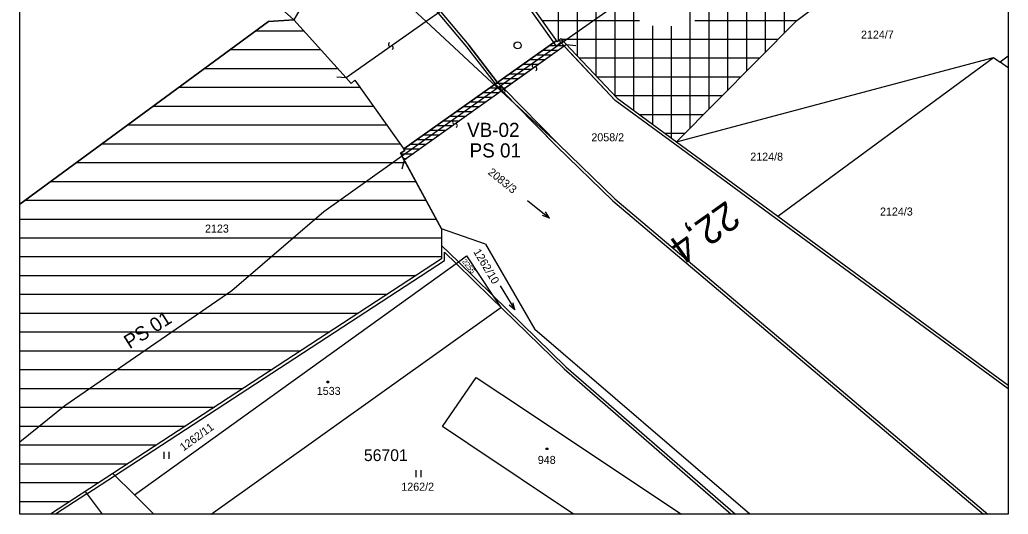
# Model space of a CAD drawing. Extents: x -792659 to -786947, y -1118170 to -1109641.
# Drawn here: x -792453.4 to -792348.4, y -1109997.6 to -1109945.1 of the extents above; entities that cross this region are included whole.
import ezdxf

# ---------------------------------------------------------------- set-up
doc = ezdxf.new("R2010")
doc.units = 0
doc.layers.add('1', color=7, linetype='Continuous')

# ---------------------------------------------------------------- blocks, each defined once
blk = doc.blocks.new('Z4022')
at = {"layer": '1'}
for p, q in [((-0.1, 0.1), (0.2, 0.1)), ((-0.1, -0.2), (-0.1, 0.1)), ((0.2, 0.1), (0.2, -0.2)), ((0.2, -0.2), (-0.1, -0.2))]:
    blk.add_line(p, q, dxfattribs=at)
blk = doc.blocks.new('Z42000')
at = {"layer": '1'}
blk.add_line((0, 0), (-0.7, -0.7), dxfattribs=at)
blk = doc.blocks.new('Z30602')
at = {"layer": '1'}
for p, q in [((-0.5, 0), (-0.5, 1.5)), ((0.5, 1.5), (0.5, 0))]:
    blk.add_line(p, q, dxfattribs=at)
blk = doc.blocks.new('Z8021')
at = {"layer": '1'}
for p, q in [((-3, 0), (3, 0)), ((3, 0), (1.5, 0.5)), ((3, 0), (1.5, -0.5))]:
    blk.add_line(p, q, dxfattribs=at)

msp = doc.modelspace()

# ---------------------------------------------------------------- linework, layer by layer
at = {"layer": '1'}
for p, q in [((-792372.2, -1109946.49), (-792372.2, -1109865.86)), ((-792376.2, -1109950.53), (-792376.2, -1109867.84)), ((-792374.2, -1109948.51), (-792374.2, -1109866.85)), ((-792378.2, -1109952.54), (-792378.2, -1109868.83)), ((-792380.2, -1109954.56), (-792380.2, -1109869.82)), ((-792382.2, -1109956.58), (-792382.2, -1109870.81)), ((-792392.2, -1109951.08), (-792392.2, -1109882.8)), ((-792394.2, -1109948.95), (-792394.2, -1109884.32)), ((-792396.2, -1109947.31), (-792396.2, -1109885.85)), ((-792390.2, -1109953.09), (-792390.2, -1109918.38)), ((-792388.2, -1109954.75), (-792388.2, -1109918.33)), ((-792410.26, -1109945.28), (-792419.34, -1109936.86)), ((-792420.84, -1109939.05), (-792424.33, -1109945.11)), ((-792396.41, -1109947.92), (-792402.08, -1109939.9)), ((-792401.63, -1109940.01), (-792396.36, -1109947.46)), ((-792389.4, -1109943.05), (-792401.43, -1109951.47)), ((-792424.33, -1109945.11), (-792425.94, -1109943.64)), ((-792408.74, -1109944.21), (-792410.26, -1109945.28)), ((-792408.74, -1109944.21), (-792405.73, -1109947.8)), ((-792427.01, -1109945.27), (-792453.43, -1109964.69)), ((-792427.01, -1109945.27), (-792453.43, -1109964.69)), ((-792424.33, -1109945.11), (-792427.01, -1109945.27)), ((-792424.33, -1109945.11), (-792427.01, -1109945.27)), ((-792424.33, -1109945.11), (-792418.77, -1109951.27)), ((-792424.33, -1109945.11), (-792418.77, -1109951.27)), ((-792410.26, -1109945.28), (-792418.77, -1109951.27)), ((-792402.3, -1109952.67), (-792410.26, -1109945.28)), ((-792402.3, -1109952.67), (-792410.26, -1109945.28)), ((-792397.99, -1109945.16), (-792387.61, -1109945.16)), ((-792381.73, -1109945.16), (-792370.88, -1109945.16)), ((-792428.37, -1109946.27), (-792423.28, -1109946.27)), ((-792386.2, -1109956.22), (-792386.2, -1109945.76)), ((-792384.2, -1109957.69), (-792384.2, -1109945.79)), ((-792396.44, -1109947.34), (-792412.63, -1109958.83)), ((-792396.36, -1109947.46), (-792396.44, -1109947.34)), ((-792396.41, -1109947.92), (-792395.97, -1109947.51)), ((-792396.36, -1109947.46), (-792395.96, -1109947.08)), ((-792395.96, -1109947.08), (-792396.36, -1109947.46)), ((-792396.22, -1109947.33), (-792395.73, -1109947.33)), ((-792395.97, -1109947.51), (-792390.18, -1109953.67)), ((-792395.96, -1109947.08), (-792395.36, -1109947.72)), ((-792395.36, -1109947.72), (-792395.96, -1109947.08)), ((-792395.89, -1109947.16), (-792372.86, -1109947.16)), ((-792431.09, -1109948.27), (-792421.48, -1109948.27)), ((-792402.71, -1109951.72), (-792405.73, -1109947.8)), ((-792405.73, -1109947.8), (-792402.71, -1109951.72)), ((-792395.36, -1109947.72), (-792401.99, -1109952.45)), ((-792397.83, -1109948.33), (-792396.21, -1109948.33)), ((-792397.13, -1109947.83), (-792395.51, -1109947.83)), ((-792394.9, -1109948.21), (-792395.36, -1109947.72)), ((-792389.98, -1109953.44), (-792394.9, -1109948.21)), ((-792399.24, -1109949.33), (-792397.61, -1109949.33)), ((-792398.54, -1109948.83), (-792396.92, -1109948.83)), ((-792394.01, -1109949.16), (-792374.85, -1109949.16)), ((-792383.68, -1109958.07), (-792350, -1109949.1)), ((-792372.92, -1109965.97), (-792350, -1109949.1)), ((-792350, -1109949.1), (-792349.29, -1109949.6)), ((-792348.43, -1109948.95), (-792349.29, -1109949.6)), ((-792348.43, -1109950.2), (-792349.29, -1109949.6)), ((-792433.81, -1109950.27), (-792419.67, -1109950.27)), ((-792400.65, -1109950.33), (-792399.02, -1109950.33)), ((-792399.95, -1109949.83), (-792398.32, -1109949.83)), ((-792401.43, -1109951.47), (-792421.14, -1109965.5)), ((-792418.77, -1109951.27), (-792419.76, -1109951.21)), ((-792418.22, -1109951.87), (-792418.77, -1109951.27)), ((-792418.77, -1109951.27), (-792418.22, -1109951.87)), ((-792418.22, -1109951.87), (-792417.83, -1109951.51)), ((-792418.22, -1109951.87), (-792417.83, -1109951.51)), ((-792417.83, -1109951.51), (-792412.51, -1109959)), ((-792417.83, -1109951.51), (-792412.51, -1109959)), ((-792402.77, -1109951.83), (-792401.12, -1109951.83)), ((-792402.71, -1109951.72), (-792401.99, -1109952.45)), ((-792402.71, -1109951.72), (-792401.99, -1109952.45)), ((-792402.06, -1109951.33), (-792400.42, -1109951.33)), ((-792401.36, -1109950.83), (-792399.72, -1109950.83)), ((-792392.12, -1109951.16), (-792376.83, -1109951.16)), ((-792436.53, -1109952.27), (-792417.29, -1109952.27)), ((-792402.3, -1109952.67), (-792412.59, -1109960.02)), ((-792404.18, -1109952.83), (-792402.52, -1109952.83)), ((-792403.47, -1109952.33), (-792401.82, -1109952.33)), ((-792402.94, -1109951.92), (-792396.42, -1109958.53)), ((-792401.99, -1109952.45), (-792402.3, -1109952.67)), ((-792396.21, -1109958.32), (-792402.3, -1109952.67)), ((-792401.99, -1109952.45), (-792396.21, -1109958.32)), ((-792405.58, -1109953.83), (-792403.92, -1109953.83)), ((-792404.88, -1109953.33), (-792403.22, -1109953.33)), ((-792390.24, -1109953.16), (-792378.81, -1109953.16)), ((-792389.98, -1109953.44), (-792383.68, -1109958.07)), ((-792439.26, -1109954.27), (-792415.87, -1109954.27)), ((-792406.99, -1109954.83), (-792405.32, -1109954.83)), ((-792406.29, -1109954.33), (-792404.62, -1109954.33)), ((-792408.4, -1109955.83), (-792406.72, -1109955.83)), ((-792407.7, -1109955.33), (-792406.02, -1109955.33)), ((-792387.64, -1109955.16), (-792380.8, -1109955.16)), ((-792441.98, -1109956.27), (-792414.45, -1109956.27)), ((-792409.81, -1109956.83), (-792408.12, -1109956.83)), ((-792409.11, -1109956.33), (-792407.42, -1109956.33)), ((-792411.22, -1109957.83), (-792409.52, -1109957.83)), ((-792410.52, -1109957.33), (-792408.82, -1109957.33)), ((-792384.92, -1109957.16), (-792382.78, -1109957.16)), ((-792383.68, -1109958.07), (-792372.92, -1109965.97)), ((-792444.7, -1109958.27), (-792413.03, -1109958.27)), ((-792412.51, -1109959), (-792413, -1109959.27)), ((-792412.51, -1109959), (-792413, -1109959.27)), ((-792412.63, -1109958.83), (-792410.92, -1109958.83)), ((-792411.93, -1109958.33), (-792410.22, -1109958.33)), ((-792396.21, -1109958.32), (-792390.22, -1109964.13)), ((-792413, -1109959.27), (-792412.59, -1109960.02)), ((-792413, -1109959.27), (-792408.62, -1109967.32)), ((-792412.97, -1109959.33), (-792411.62, -1109959.33)), ((-792412.59, -1109960.02), (-792412.84, -1109960.98)), ((-792412.69, -1109959.83), (-792412.32, -1109959.83)), ((-792408.62, -1109967.32), (-792412.59, -1109960.02)), ((-792447.42, -1109960.27), (-792412.46, -1109960.27)), ((-792450.14, -1109962.27), (-792411.37, -1109962.27)), ((-792452.86, -1109964.27), (-792410.28, -1109964.27)), ((-792390.22, -1109964.13), (-792350.58, -1109997.64)), ((-792453.43, -1109966.27), (-792409.19, -1109966.27)), ((-792421.14, -1109965.5), (-792430.91, -1109973.9)), ((-792372.92, -1109965.97), (-792348.43, -1109983.94)), ((-792408.62, -1109967.32), (-792408.62, -1109969.07)), ((-792403.95, -1109968.95), (-792408.62, -1109967.32)), ((-792408.62, -1109967.32), (-792408.62, -1109969.07)), ((-792453.43, -1109968.27), (-792408.62, -1109968.27)), ((-792408.62, -1109969.07), (-792406.84, -1109970.81)), ((-792408.62, -1109969.07), (-792408.62, -1109970.51)), ((-792408.62, -1109969.07), (-792408.62, -1109970.51)), ((-792403.95, -1109968.95), (-792398.71, -1109978)), ((-792453.43, -1109970.27), (-792408.62, -1109970.27)), ((-792408.62, -1109970.51), (-792443.53, -1109993.3)), ((-792408.62, -1109970.51), (-792443.53, -1109993.3)), ((-792406.84, -1109970.81), (-792405.98, -1109970.19)), ((-792405.98, -1109970.19), (-792403.21, -1109974.35)), ((-792441.26, -1109995.57), (-792406.84, -1109970.81)), ((-792406.84, -1109970.81), (-792403.21, -1109974.35)), ((-792453.43, -1109972.27), (-792411.32, -1109972.27)), ((-792430.91, -1109973.9), (-792448.63, -1109986.11)), ((-792453.43, -1109974.27), (-792414.38, -1109974.27)), ((-792403.21, -1109974.35), (-792402.34, -1109975.66)), ((-792403.21, -1109974.35), (-792395.41, -1109981.97)), ((-792433.1, -1109997.64), (-792402.34, -1109975.66)), ((-792453.43, -1109976.27), (-792417.44, -1109976.27)), ((-792375.89, -1109997.64), (-792398.71, -1109978)), ((-792453.43, -1109978.27), (-792420.51, -1109978.27)), ((-792453.43, -1109980.27), (-792423.57, -1109980.27)), ((-792453.43, -1109982.27), (-792426.63, -1109982.27)), ((-792395.41, -1109981.97), (-792377.41, -1109997.64)), ((-792408.53, -1109988.32), (-792404.94, -1109983.1)), ((-792404.94, -1109983.1), (-792402.24, -1109984.9)), ((-792453.43, -1109984.27), (-792429.7, -1109984.27)), ((-792402.24, -1109984.9), (-792383.15, -1109997.64)), ((-792448.63, -1109986.11), (-792453.43, -1109989.98)), ((-792453.43, -1109986.27), (-792432.76, -1109986.27)), ((-792453.43, -1109988.27), (-792435.83, -1109988.27)), ((-792405.83, -1109990.13), (-792408.53, -1109988.32)), ((-792453.43, -1109990.27), (-792438.89, -1109990.27)), ((-792394.62, -1109997.64), (-792405.83, -1109990.13)), ((-792453.43, -1109992.27), (-792441.95, -1109992.27)), ((-792443.53, -1109993.3), (-792450.18, -1109997.64)), ((-792443.53, -1109993.3), (-792450.18, -1109997.64)), ((-792443.53, -1109993.3), (-792441.26, -1109995.57)), ((-792443.52, -1109993.27), (-792443.48, -1109993.27)), ((-792453.43, -1109994.27), (-792445.02, -1109994.27)), ((-792441.26, -1109995.57), (-792439.18, -1109997.64)), ((-792453.43, -1109996.27), (-792448.08, -1109996.27))]:
    msp.add_line(p, q, dxfattribs=at)
for points in [[(-792453.43, -1109849.14), (-792348.43, -1109849.14), (-792348.43, -1109997.64), (-792453.43, -1109997.64)], [(-792453.43, -1109964.69), (-792427.01, -1109945.27), (-792424.33, -1109945.11), (-792418.77, -1109951.27), (-792418.22, -1109951.87), (-792417.83, -1109951.51), (-792412.51, -1109959), (-792413, -1109959.27), (-792412.59, -1109960.02), (-792408.62, -1109967.32), (-792408.62, -1109969.07), (-792408.62, -1109970.51), (-792443.53, -1109993.3), (-792450.18, -1109997.64), (-792453.43, -1109997.64)], [(-792396.44, -1109947.34), (-792396.36, -1109947.46), (-792395.96, -1109947.08), (-792395.36, -1109947.72), (-792402.3, -1109952.67), (-792412.59, -1109960.02), (-792413, -1109959.27), (-792412.51, -1109959), (-792412.63, -1109958.83)]]:
    msp.add_lwpolyline(points, close=True, dxfattribs=at)
for points in [[(-792348.43, -1109984.31), (-792373.1, -1109966.21), (-792383.86, -1109958.31), (-792390.18, -1109953.67), (-792395.12, -1109948.42), (-792395.58, -1109947.93), (-792395.97, -1109947.51), (-792396.41, -1109947.92), (-792402.08, -1109939.9), (-792401.49, -1109939.6), (-792401.69, -1109939.2), (-792404.73, -1109933.02), (-792404.68, -1109931.37), (-792406.07, -1109932.97), (-792409.86, -1109929.29), (-792408.37, -1109927.32), (-792424.63, -1109907.11), (-792386.4, -1109878.01), (-792389.56, -1109874.13), (-792363.68, -1109861.3), (-792350.08, -1109854.55), (-792348.43, -1109853.94)], [(-792421.13, -1109932.36), (-792420.3, -1109934.93), (-792418.93, -1109936.41), (-792417.77, -1109933.91), (-792408.97, -1109944.4), (-792405.96, -1109947.99), (-792402.94, -1109951.92), (-792402.2, -1109952.66), (-792396.42, -1109958.53), (-792390.42, -1109964.35), (-792351.04, -1109997.64)], [(-792383.68, -1109958.07), (-792370.89, -1109945.17), (-792367.46, -1109942.54)], [(-792446.31, -1109995.46), (-792443.37, -1109993.55), (-792408.32, -1109970.67), (-792408.32, -1109969.78), (-792407.05, -1109971.02), (-792403.42, -1109974.56), (-792395.61, -1109982.19), (-792377.87, -1109997.64)], [(-792446.31, -1109995.46), (-792449.65, -1109997.64)], [(-792446.47, -1109995.21), (-792444.67, -1109997.64)]]:
    msp.add_lwpolyline(points, dxfattribs=at)
msp.add_circle((-792400.55, -1109947.82), 0.375, dxfattribs=at)
for centre, start, end in [((-792414.09, -1109947.72), 111.4312, 291.4312), ((-792413.95, -1109948.07), 291.4312, 111.4312), ((-792398.82, -1109949.96), 111.4312, 291.4312), ((-792398.68, -1109950.31), 291.4312, 111.4312), ((-792402.21, -1109952.36), 111.4312, 291.4312), ((-792402.07, -1109952.71), 291.4312, 111.4312), ((-792407.27, -1109955.99), 111.4312, 291.4312), ((-792407.13, -1109956.34), 291.4312, 111.4312)]:
    msp.add_arc(centre, 0.188, start, end, dxfattribs=at)

# ---------------------------------------------------------------- block references
for p, rotation in [((-792395.36, -1109947.72), 128.8627), ((-792418.77, -1109951.27), -48.4683), ((-792412.59, -1109960.02), 30.2171)]:
    msp.add_blockref('Z42000', p, dxfattribs=dict(at, rotation=rotation))
at = {"layer": '1', "xscale": 0.5, "yscale": 0.5}
for p, rotation in [((-792398.33, -1109965.24), -38.61369999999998), ((-792401.63, -1109974.66), -58.40800000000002)]:
    msp.add_blockref('Z8021', p, dxfattribs=dict(at, rotation=rotation))
for name, p in [('Z4022', (-792420.73, -1109983.56)), ('Z4022', (-792397.45, -1109990.66)), ('Z30602', (-792437.85, -1109991.76)), ('Z30602', (-792411.08, -1109993.7))]:
    msp.add_blockref(name, p, dxfattribs=at)

# ---------------------------------------------------------------- texts
at = {"layer": '1'}
for s, height, p in [('2124/7', 0.85, (-792364.07, -1109947.1)), ('VB-02', 1.5, (-792405.92, -1109957.55)), ('2058/2', 0.85, (-792392.71, -1109958.01)), ('PS 01', 1.5, (-792405.65, -1109959.73)), ('2124/8', 0.85, (-792375.83, -1109960.07)), ('2124/3', 0.85, (-792362.05, -1109965.9)), ('2123', 0.85, (-792433.75, -1109967.71)), ('1533', 0.85, (-792421.88, -1109984.96)), ('56701', 1.25, (-792416.87, -1109991.99)), ('948', 0.85, (-792398.4, -1109992.29)), ('1262/2', 0.85, (-792412.9, -1109995.14))]:
    msp.add_text(s, height=height, dxfattribs=at).set_placement(p)
for s, height, rotation, p in [('2083/3', 0.85, 320.9767, (-792403.77, -1109961.43)), ('22,4', 3, 215.3609, (-792378.33, -1109964.23)), ('1262/10', 0.85, 300.9486, (-792405.28, -1109969.75)), ('2255', 0.558, 309.0532, (-792406.49, -1109970.8)), ('PS 01', 1.5, 32.364, (-792441.76, -1109980.12)), ('1262/11', 0.85, 36.1626, (-792436.04, -1109990.98))]:
    msp.add_text(s, height=height, rotation=rotation, dxfattribs=at).set_placement(p)

doc.saveas('drawing.dxf')
